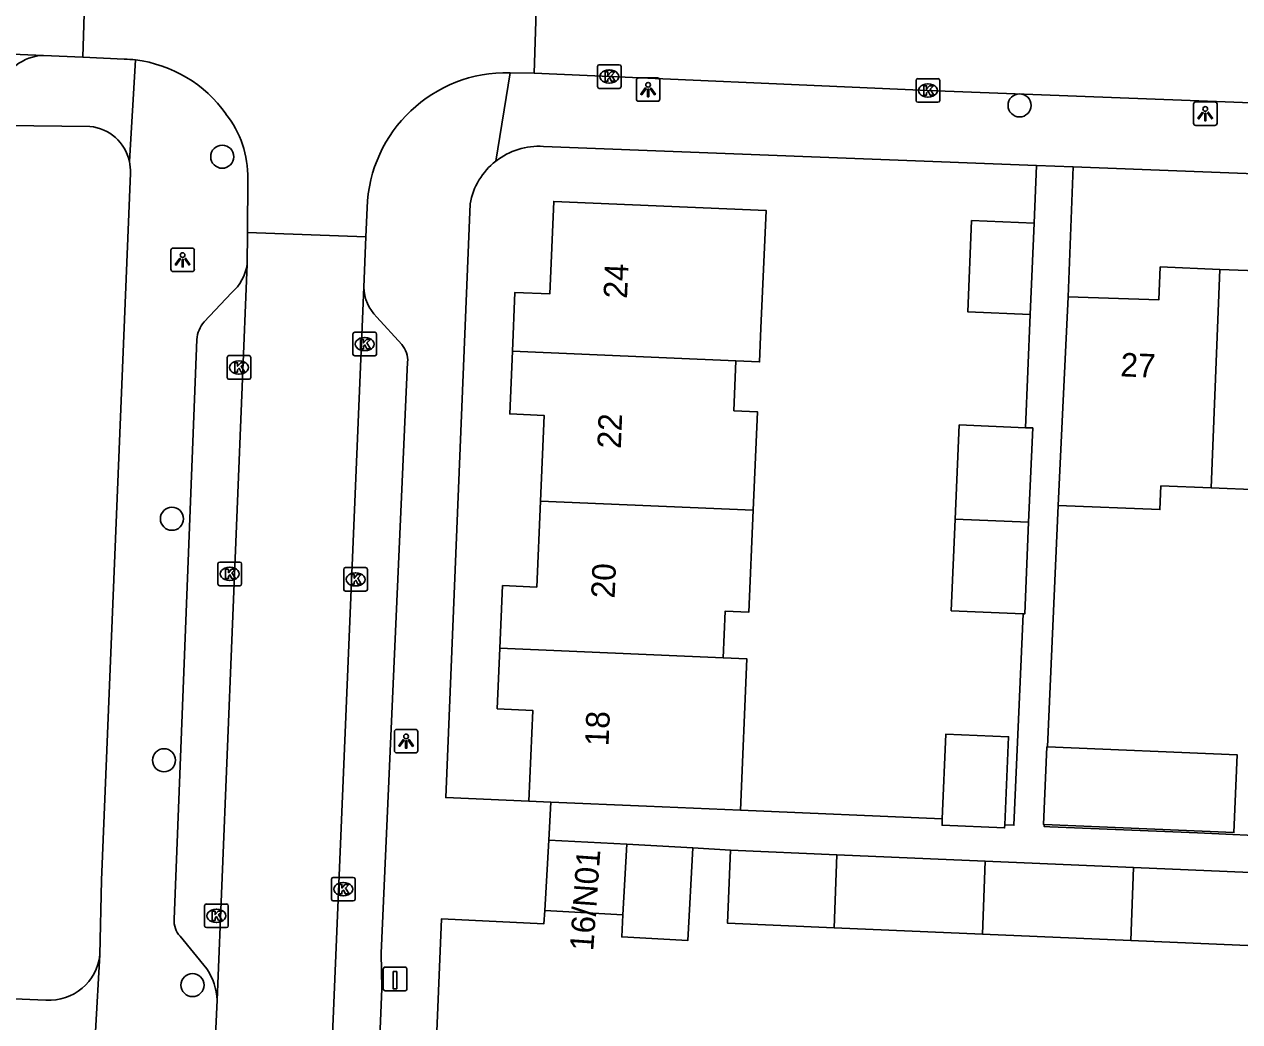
# Model space of a CAD drawing. Extents: x 160732 to 162105, y 387428 to 388479.
# Drawn here: x 161250.8 to 161302.4, y 387575 to 387617.3 of the extents above; entities that cross this region are included whole.
import ezdxf

# ---------------------------------------------------------------- set-up
doc = ezdxf.new("R2010")
doc.units = 0
for name, color, linetype in [('IMGEO_Boom', 7, 'Continuous'), ('IMGEO_Kolk', 7, 'Continuous'), ('IMGEO_Laadpaal', 7, 'Continuous'), ('IMGEO_Lichtpunt', 7, 'Continuous'), ('IMGEO_Pand', 7, 'Continuous'), ('IMGEO_Pand_nummerreeks', 7, 'Continuous'), ('IMGEO_Rijbaan_lokaal_open', 7, 'Continuous'), ('IMGEO_Voetpad_open', 7, 'Continuous')]:
    doc.layers.add(name, color=color, linetype=linetype)

msp = doc.modelspace()

# ---------------------------------------------------------------- linework, layer by layer
at = {"layer": 'IMGEO_Boom'}
for centre in [(161293.062, 387613.849), (161259.203, 387611.671), (161257.067, 387596.302), (161256.731, 387586.051), (161257.941, 387576.507)]:
    msp.add_circle(centre, 0.489, dxfattribs=at)
at = {"layer": 'IMGEO_Kolk'}
for p, q in [((161275.14, 387614.646), (161275.14, 387615.498)), ((161275.215, 387615.572), (161276.067, 387615.572)), ((161276.141, 387615.498), (161276.141, 387614.646)), ((161275.628, 387615.352), (161275.653, 387615.352)), ((161288.671, 387614.058), (161288.671, 387614.91)), ((161288.746, 387614.984), (161289.598, 387614.984)), ((161289.672, 387614.91), (161289.672, 387614.058)), ((161276.067, 387614.572), (161275.215, 387614.572)), ((161275.651, 387614.792), (161275.626, 387614.792)), ((161289.159, 387614.764), (161289.184, 387614.764)), ((161289.598, 387613.984), (161288.746, 387613.984)), ((161289.182, 387614.204), (161289.157, 387614.204)), ((161264.756, 387603.293), (161264.756, 387604.145)), ((161264.831, 387604.219), (161265.683, 387604.219)), ((161265.757, 387604.145), (161265.757, 387603.293)), ((161265.244, 387603.999), (161265.269, 387603.999)), ((161259.414, 387602.3), (161259.414, 387603.152)), ((161259.489, 387603.226), (161260.341, 387603.226)), ((161259.902, 387603.006), (161259.927, 387603.006)), ((161260.415, 387603.152), (161260.415, 387602.3)), ((161265.683, 387603.219), (161264.831, 387603.219)), ((161265.267, 387603.439), (161265.242, 387603.439)), ((161260.341, 387602.226), (161259.489, 387602.226)), ((161259.925, 387602.446), (161259.9, 387602.446)), ((161259.022, 387593.536), (161259.022, 387594.388)), ((161259.097, 387594.462), (161259.949, 387594.462)), ((161259.51, 387594.242), (161259.535, 387594.242)), ((161260.023, 387594.388), (161260.023, 387593.536)), ((161264.441, 387594.23), (161265.293, 387594.23)), ((161264.366, 387593.304), (161264.366, 387594.156)), ((161264.854, 387594.01), (161264.879, 387594.01)), ((161265.367, 387594.156), (161265.367, 387593.304)), ((161259.949, 387593.462), (161259.097, 387593.462)), ((161259.533, 387593.682), (161259.508, 387593.682)), ((161265.293, 387593.23), (161264.441, 387593.23)), ((161264.877, 387593.45), (161264.852, 387593.45)), ((161263.843, 387580.154), (161263.843, 387581.006)), ((161263.918, 387581.08), (161264.77, 387581.08)), ((161264.331, 387580.86), (161264.356, 387580.86)), ((161264.844, 387581.006), (161264.844, 387580.154)), ((161264.354, 387580.3), (161264.329, 387580.3)), ((161258.457, 387579.024), (161258.457, 387579.876)), ((161258.532, 387579.95), (161259.384, 387579.95)), ((161259.458, 387579.876), (161259.458, 387579.024)), ((161264.77, 387580.08), (161263.918, 387580.08)), ((161258.945, 387579.73), (161258.97, 387579.73)), ((161259.384, 387578.95), (161258.532, 387578.95)), ((161258.968, 387579.17), (161258.943, 387579.17))]:
    msp.add_line(p, q, dxfattribs=at)
for points in [[(161275.14, 387614.646), (161275.14, 387615.498)], [(161275.215, 387615.572), (161276.067, 387615.572)], [(161276.141, 387615.498), (161276.141, 387614.646)], [(161275.461, 387615.272), (161275.584, 387615.272), (161275.584, 387615.121), (161275.714, 387615.272), (161275.878, 387615.272), (161275.732, 387615.121), (161275.885, 387614.872), (161275.733, 387614.872), (161275.648, 387615.036), (161275.584, 387614.969), (161275.584, 387614.872), (161275.461, 387614.872), (161275.461, 387615.272)], [(161288.671, 387614.058), (161288.671, 387614.91)], [(161288.746, 387614.984), (161289.598, 387614.984)], [(161289.672, 387614.91), (161289.672, 387614.058)], [(161276.067, 387614.572), (161275.215, 387614.572)], [(161288.992, 387614.684), (161289.115, 387614.684), (161289.115, 387614.533), (161289.245, 387614.684), (161289.409, 387614.684), (161289.263, 387614.533), (161289.416, 387614.284), (161289.264, 387614.284), (161289.179, 387614.448), (161289.115, 387614.381), (161289.115, 387614.284), (161288.992, 387614.284), (161288.992, 387614.684)], [(161289.598, 387613.984), (161288.746, 387613.984)], [(161264.756, 387603.293), (161264.756, 387604.145)], [(161264.831, 387604.219), (161265.683, 387604.219)], [(161265.757, 387604.145), (161265.757, 387603.293)], [(161265.077, 387603.919), (161265.2, 387603.919), (161265.2, 387603.768), (161265.33, 387603.919), (161265.494, 387603.919), (161265.348, 387603.768), (161265.501, 387603.519), (161265.349, 387603.519), (161265.264, 387603.683), (161265.2, 387603.616), (161265.2, 387603.519), (161265.077, 387603.519), (161265.077, 387603.919)], [(161259.414, 387602.3), (161259.414, 387603.152)], [(161259.489, 387603.226), (161260.341, 387603.226)], [(161260.415, 387603.152), (161260.415, 387602.3)], [(161265.683, 387603.219), (161264.831, 387603.219)], [(161259.735, 387602.926), (161259.858, 387602.926), (161259.858, 387602.775), (161259.988, 387602.926), (161260.152, 387602.926), (161260.006, 387602.775), (161260.159, 387602.526), (161260.007, 387602.526), (161259.922, 387602.69), (161259.858, 387602.623), (161259.858, 387602.526), (161259.735, 387602.526), (161259.735, 387602.926)], [(161260.341, 387602.226), (161259.489, 387602.226)], [(161259.022, 387593.536), (161259.022, 387594.388)], [(161259.097, 387594.462), (161259.949, 387594.462)], [(161260.023, 387594.388), (161260.023, 387593.536)], [(161264.441, 387594.23), (161265.293, 387594.23)], [(161259.343, 387594.162), (161259.466, 387594.162), (161259.466, 387594.011), (161259.596, 387594.162), (161259.76, 387594.162), (161259.614, 387594.011), (161259.767, 387593.762), (161259.615, 387593.762), (161259.53, 387593.926), (161259.466, 387593.859), (161259.466, 387593.762), (161259.343, 387593.762), (161259.343, 387594.162)], [(161264.366, 387593.304), (161264.366, 387594.156)], [(161264.687, 387593.93), (161264.81, 387593.93), (161264.81, 387593.779), (161264.94, 387593.93), (161265.104, 387593.93), (161264.958, 387593.779), (161265.111, 387593.53), (161264.959, 387593.53), (161264.874, 387593.694), (161264.81, 387593.627), (161264.81, 387593.53), (161264.687, 387593.53), (161264.687, 387593.93)], [(161265.367, 387594.156), (161265.367, 387593.304)], [(161259.949, 387593.462), (161259.097, 387593.462)], [(161265.293, 387593.23), (161264.441, 387593.23)], [(161263.843, 387580.154), (161263.843, 387581.006)], [(161263.918, 387581.08), (161264.77, 387581.08)], [(161264.844, 387581.006), (161264.844, 387580.154)], [(161264.164, 387580.78), (161264.287, 387580.78), (161264.287, 387580.629), (161264.417, 387580.78), (161264.581, 387580.78), (161264.435, 387580.629), (161264.588, 387580.38), (161264.436, 387580.38), (161264.351, 387580.544), (161264.287, 387580.477), (161264.287, 387580.38), (161264.164, 387580.38), (161264.164, 387580.78)], [(161258.457, 387579.024), (161258.457, 387579.876)], [(161258.532, 387579.95), (161259.384, 387579.95)], [(161259.458, 387579.876), (161259.458, 387579.024)], [(161264.77, 387580.08), (161263.918, 387580.08)], [(161258.778, 387579.65), (161258.901, 387579.65), (161258.901, 387579.499), (161259.031, 387579.65), (161259.195, 387579.65), (161259.049, 387579.499), (161259.202, 387579.25), (161259.05, 387579.25), (161258.965, 387579.414), (161258.901, 387579.347), (161258.901, 387579.25), (161258.778, 387579.25), (161258.778, 387579.65)], [(161259.384, 387578.95), (161258.532, 387578.95)]]:
    msp.add_lwpolyline(points, dxfattribs=at)
for centre, start, end in [((161275.217, 387615.496), 91.552, 178.448), ((161275.217, 387615.496), 91.552, 178.448), ((161276.065, 387615.496), 1.552, 88.448), ((161276.065, 387615.496), 1.552, 88.448), ((161288.748, 387614.908), 91.552, 178.448), ((161288.748, 387614.908), 91.552, 178.448), ((161289.596, 387614.908), 1.552, 88.448), ((161289.596, 387614.908), 1.552, 88.448), ((161275.217, 387614.648), 181.552, 268.448), ((161275.217, 387614.648), 181.552, 268.448), ((161276.065, 387614.648), 271.552, 358.448), ((161276.065, 387614.648), 271.552, 358.448), ((161288.748, 387614.06), 181.552, 268.448), ((161288.748, 387614.06), 181.552, 268.448), ((161289.596, 387614.06), 271.552, 358.448), ((161289.596, 387614.06), 271.552, 358.448), ((161264.833, 387604.143), 91.552, 178.448), ((161264.833, 387604.143), 91.552, 178.448), ((161265.681, 387604.143), 1.552, 88.448), ((161265.681, 387604.143), 1.552, 88.448), ((161259.491, 387603.15), 91.552, 178.448), ((161259.491, 387603.15), 91.552, 178.448), ((161260.339, 387603.15), 1.552, 88.448), ((161260.339, 387603.15), 1.552, 88.448), ((161264.833, 387603.295), 181.552, 268.448), ((161264.833, 387603.295), 181.552, 268.448), ((161265.681, 387603.295), 271.552, 358.448), ((161265.681, 387603.295), 271.552, 358.448), ((161259.491, 387602.302), 181.552, 268.448), ((161259.491, 387602.302), 181.552, 268.448), ((161260.339, 387602.302), 271.552, 358.448), ((161260.339, 387602.302), 271.552, 358.448), ((161259.099, 387594.386), 91.552, 178.448), ((161259.099, 387594.386), 91.552, 178.448), ((161259.947, 387594.386), 1.552, 88.448), ((161259.947, 387594.386), 1.552, 88.448), ((161264.443, 387594.154), 91.552, 178.448), ((161264.443, 387594.154), 91.552, 178.448), ((161265.291, 387594.154), 1.552, 88.448), ((161265.291, 387594.154), 1.552, 88.448), ((161259.099, 387593.538), 181.552, 268.448), ((161259.099, 387593.538), 181.552, 268.448), ((161259.947, 387593.538), 271.552, 358.448), ((161259.947, 387593.538), 271.552, 358.448), ((161264.443, 387593.306), 181.552, 268.448), ((161264.443, 387593.306), 181.552, 268.448), ((161265.291, 387593.306), 271.552, 358.448), ((161265.291, 387593.306), 271.552, 358.448), ((161263.92, 387581.004), 91.552, 178.448), ((161263.92, 387581.004), 91.552, 178.448), ((161264.768, 387581.004), 1.552, 88.448), ((161264.768, 387581.004), 1.552, 88.448), ((161258.534, 387579.874), 91.552, 178.448), ((161258.534, 387579.874), 91.552, 178.448), ((161259.382, 387579.874), 1.552, 88.448), ((161259.382, 387579.874), 1.552, 88.448), ((161263.92, 387580.156), 181.552, 268.448), ((161263.92, 387580.156), 181.552, 268.448), ((161264.768, 387580.156), 271.552, 358.448), ((161264.768, 387580.156), 271.552, 358.448), ((161258.534, 387579.026), 181.552, 268.448), ((161258.534, 387579.026), 181.552, 268.448), ((161259.382, 387579.026), 271.552, 358.448), ((161259.382, 387579.026), 271.552, 358.448)]:
    msp.add_arc(centre, 0.0765, start, end, dxfattribs=at)
for centre, major_axis, ratio, start_param, end_param in [((161275.627, 387615.072), (-0.387, 0.002), 0.722429, 4.712389, 7.853982), ((161275.652, 387615.072), (-0.39, 0.002), 0.717154, 1.570796, 4.712389), ((161289.158, 387614.484), (-0.387, 0.002), 0.722429, 4.712389, 7.853982), ((161289.183, 387614.484), (-0.39, 0.002), 0.717154, 1.570796, 4.712389), ((161265.243, 387603.719), (-0.387, 0.002), 0.722429, 4.712389, 7.853982), ((161265.268, 387603.719), (-0.39, 0.002), 0.717154, 1.570796, 4.712389), ((161259.901, 387602.726), (-0.387, 0.002), 0.722429, 4.712389, 7.853982), ((161259.926, 387602.726), (-0.39, 0.002), 0.717154, 1.570796, 4.712389), ((161259.509, 387593.962), (-0.387, 0.002), 0.722429, 4.712389, 7.853982), ((161259.534, 387593.962), (-0.39, 0.002), 0.717154, 1.570796, 4.712389), ((161264.853, 387593.73), (-0.387, 0.002), 0.722429, 4.712389, 7.853982), ((161264.878, 387593.73), (-0.39, 0.002), 0.717154, 1.570796, 4.712389), ((161264.33, 387580.58), (-0.387, 0.002), 0.722429, 4.712389, 7.853982), ((161264.355, 387580.58), (-0.39, 0.002), 0.717154, 1.570796, 4.712389), ((161258.944, 387579.45), (-0.387, 0.002), 0.722429, 4.712389, 7.853982), ((161258.969, 387579.45), (-0.39, 0.002), 0.717154, 1.570796, 4.712389)]:
    msp.add_ellipse(centre, major_axis=major_axis, ratio=ratio, start_param=start_param, end_param=end_param, dxfattribs=at)
at = {"layer": 'IMGEO_Laadpaal'}
for p, q in [((161266.959, 387577.27), (161266.118, 387577.27)), ((161266.959, 387577.27), (161266.118, 387577.27)), ((161267.043, 387576.354), (161267.043, 387577.195)), ((161267.043, 387576.354), (161267.043, 387577.195)), ((161266.043, 387577.186), (161266.043, 387576.345)), ((161266.043, 387577.186), (161266.043, 387576.345)), ((161266.127, 387576.27), (161266.968, 387576.27)), ((161266.127, 387576.27), (161266.968, 387576.27))]:
    msp.add_line(p, q, dxfattribs=at)
msp.add_lwpolyline([(161266.458, 387577.083), (161266.618, 387577.083), (161266.618, 387576.35), (161266.458, 387576.35), (161266.458, 387577.083)], dxfattribs=at)
for centre, start, end in [((161266.121, 387577.192), 92.4484, 184.2845), ((161266.121, 387577.192), 92.4484, 184.2845), ((161266.965, 387577.192), 2.4484, 94.2845), ((161266.965, 387577.192), 2.4484, 94.2845), ((161266.121, 387576.348), 182.4484, 274.2845), ((161266.121, 387576.348), 182.4484, 274.2845), ((161266.965, 387576.348), 272.4484, 4.2845), ((161266.965, 387576.348), 272.4484, 4.2845)]:
    msp.add_arc(centre, 0.0779, start, end, dxfattribs=at)
at = {"layer": 'IMGEO_Lichtpunt'}
for p, q in [((161276.791, 387614.924), (161276.791, 387614.117)), ((161276.791, 387614.924), (161276.791, 387614.117)), ((161277.693, 387615.019), (161276.885, 387615.019)), ((161277.693, 387615.019), (161276.885, 387615.019)), ((161277.787, 387614.117), (161277.787, 387614.924)), ((161277.787, 387614.117), (161277.787, 387614.924)), ((161276.885, 387614.023), (161277.693, 387614.023)), ((161276.885, 387614.023), (161277.693, 387614.023)), ((161300.452, 387613.902), (161300.452, 387613.095)), ((161300.452, 387613.902), (161300.452, 387613.095)), ((161301.354, 387613.997), (161300.546, 387613.997)), ((161301.354, 387613.997), (161300.546, 387613.997)), ((161301.448, 387613.095), (161301.448, 387613.902)), ((161301.448, 387613.095), (161301.448, 387613.902)), ((161300.546, 387613.001), (161301.354, 387613.001)), ((161300.546, 387613.001), (161301.354, 387613.001)), ((161257.023, 387607.699), (161257.023, 387606.892)), ((161257.023, 387607.699), (161257.023, 387606.892)), ((161257.925, 387607.794), (161257.117, 387607.794)), ((161257.925, 387607.794), (161257.117, 387607.794)), ((161258.019, 387606.892), (161258.019, 387607.699)), ((161258.019, 387606.892), (161258.019, 387607.699)), ((161257.117, 387606.798), (161257.925, 387606.798)), ((161257.117, 387606.798), (161257.925, 387606.798)), ((161266.514, 387587.265), (161266.514, 387586.458)), ((161266.514, 387587.265), (161266.514, 387586.458)), ((161267.416, 387587.36), (161266.608, 387587.36)), ((161267.416, 387587.36), (161266.608, 387587.36)), ((161267.51, 387586.458), (161267.51, 387587.265)), ((161267.51, 387586.458), (161267.51, 387587.265)), ((161266.608, 387586.364), (161267.416, 387586.364)), ((161266.608, 387586.364), (161267.416, 387586.364))]:
    msp.add_line(p, q, dxfattribs=at)
for points in [[(161277.165, 387614.588), (161277.204, 387614.56), (161277.016, 387614.298), (161276.978, 387614.325), (161277.165, 387614.588)], [(161277.267, 387614.54), (161277.314, 387614.54), (161277.314, 387614.218), (161277.267, 387614.218), (161277.267, 387614.54)], [(161277.377, 387614.56), (161277.415, 387614.587), (161277.602, 387614.325), (161277.563, 387614.297), (161277.377, 387614.56)], [(161300.826, 387613.566), (161300.865, 387613.538), (161300.677, 387613.276), (161300.639, 387613.303), (161300.826, 387613.566)], [(161300.928, 387613.518), (161300.975, 387613.518), (161300.975, 387613.196), (161300.928, 387613.196), (161300.928, 387613.518)], [(161301.038, 387613.538), (161301.076, 387613.565), (161301.263, 387613.303), (161301.224, 387613.275), (161301.038, 387613.538)], [(161257.397, 387607.363), (161257.436, 387607.335), (161257.248, 387607.073), (161257.21, 387607.1), (161257.397, 387607.363)], [(161257.499, 387607.315), (161257.546, 387607.315), (161257.546, 387606.993), (161257.499, 387606.993), (161257.499, 387607.315)], [(161257.609, 387607.335), (161257.647, 387607.362), (161257.834, 387607.1), (161257.795, 387607.072), (161257.609, 387607.335)], [(161266.888, 387586.929), (161266.927, 387586.901), (161266.739, 387586.639), (161266.701, 387586.666), (161266.888, 387586.929)], [(161266.99, 387586.881), (161267.037, 387586.881), (161267.037, 387586.559), (161266.99, 387586.559), (161266.99, 387586.881)], [(161267.1, 387586.901), (161267.138, 387586.928), (161267.325, 387586.666), (161267.286, 387586.638), (161267.1, 387586.901)]]:
    msp.add_lwpolyline(points, dxfattribs=at)
for centre in [(161277.29, 387614.722), (161300.951, 387613.7), (161257.522, 387607.497), (161267.013, 387587.063)]:
    msp.add_circle(centre, 0.0994, dxfattribs=at)
for centre, start, end in [((161276.885, 387614.924), 90, 180), ((161276.885, 387614.924), 90, 180), ((161277.693, 387614.924), 0, 90), ((161277.693, 387614.924), 0, 90), ((161276.885, 387614.117), 180, 270), ((161276.885, 387614.117), 180, 270), ((161277.693, 387614.117), 270, 0), ((161277.693, 387614.117), 270, 360), ((161300.546, 387613.902), 90, 180), ((161300.546, 387613.902), 90, 180), ((161301.354, 387613.902), 0, 90), ((161301.354, 387613.902), 0, 90), ((161300.546, 387613.095), 180, 270), ((161300.546, 387613.095), 180, 270), ((161301.354, 387613.095), 270, 0), ((161301.354, 387613.095), 270, 360), ((161257.117, 387607.699), 90, 180), ((161257.117, 387607.699), 90, 180), ((161257.925, 387607.699), 0, 90), ((161257.925, 387607.699), 0, 90), ((161257.117, 387606.892), 180, 270), ((161257.117, 387606.892), 180, 270), ((161257.925, 387606.892), 270, 0), ((161257.925, 387606.892), 270, 360), ((161266.608, 387587.265), 90, 180), ((161266.608, 387587.265), 90, 180), ((161267.416, 387587.265), 0, 90), ((161267.416, 387587.265), 0, 90), ((161266.608, 387586.458), 180, 270), ((161266.608, 387586.458), 180, 270), ((161267.416, 387586.458), 270, 0), ((161267.416, 387586.458), 270, 360)]:
    msp.add_arc(centre, 0.0946, start, end, dxfattribs=at)
at = {"layer": 'IMGEO_Pand'}
for points in [[(161271.53, 387603.417), (161271.636, 387605.91), (161273.114, 387605.847), (161273.282, 387609.775), (161282.296, 387609.389), (161282.082, 387604.394), (161282.021, 387602.964), (161281.021, 387603.007)], [(161293.518, 387604.977), (161290.86, 387605.09), (161291.025, 387608.958), (161293.683, 387608.845)], [(161293.683, 387608.845), (161293.518, 387604.977)], [(161295.134, 387605.725), (161298.979, 387605.598), (161299.035, 387606.991), (161301.569, 387606.89)], [(161301.2, 387597.613), (161301.569, 387606.89)], [(161301.569, 387606.89), (161304.303, 387606.782), (161304.245, 387605.331), (161307.807, 387605.189)], [(161294.699, 387596.865), (161294.889, 387600.732), (161295.134, 387605.725)], [(161272.718, 387597.051), (161272.873, 387600.693), (161271.416, 387600.756), (161271.53, 387603.417)], [(161271.53, 387603.417), (161281.021, 387603.007)], [(161281.021, 387603.007), (161280.93, 387600.886), (161281.93, 387600.843), (161281.751, 387596.661)], [(161290.33, 387596.291), (161290.502, 387600.289), (161293.313, 387600.169)], [(161293.45, 387596.156), (161293.621, 387600.156), (161293.313, 387600.169)], [(161301.2, 387597.613), (161299.067, 387597.699), (161299.026, 387596.69), (161294.699, 387596.865)], [(161307.455, 387596.343), (161303.206, 387596.519), (161303.248, 387597.53), (161301.2, 387597.613)], [(161270.992, 387590.81), (161271.106, 387593.468), (161272.562, 387593.406), (161272.718, 387597.051)], [(161272.718, 387597.051), (161281.751, 387596.661)], [(161281.751, 387596.661), (161281.567, 387592.341), (161280.568, 387592.383), (161280.483, 387590.4)], [(161293.213, 387592.265), (161290.164, 387592.396), (161290.33, 387596.291)], [(161290.33, 387596.291), (161293.45, 387596.156)], [(161293.213, 387592.265), (161293.283, 387592.262), (161293.45, 387596.156)], [(161272.229, 387584.319), (161272.394, 387588.17), (161270.882, 387588.235), (161270.992, 387590.81)], [(161280.483, 387590.4), (161270.992, 387590.81)], [(161280.483, 387590.4), (161281.482, 387590.357), (161281.207, 387583.935)], [(161289.783, 387583.569), (161289.936, 387587.161), (161292.594, 387587.048), (161292.435, 387583.31)], [(161294.114, 387583.32), (161294.085, 387583.321), (161294.224, 387586.624), (161294.256, 387586.623)], [(161294.256, 387586.623), (161302.303, 387586.286), (161302.165, 387582.982), (161294.114, 387583.32)], [(161273.16, 387584.279), (161272.229, 387584.319)], [(161281.207, 387583.935), (161277.225, 387584.105), (161273.16, 387584.279)], [(161292.435, 387583.31), (161292.429, 387583.18), (161289.771, 387583.293), (161289.783, 387583.569)], [(161272.905, 387579.671), (161273.067, 387582.666)], [(161273.067, 387582.666), (161276.384, 387582.486)], [(161276.222, 387579.491), (161276.384, 387582.486)], [(161276.384, 387582.486), (161279.188, 387582.334)], [(161276.222, 387579.491), (161276.171, 387578.55), (161278.975, 387578.398), (161279.188, 387582.334)], [(161280.791, 387582.236), (161280.657, 387579.141), (161285.186, 387578.945)], [(161280.791, 387582.236), (161285.302, 387582.042)], [(161285.302, 387582.042), (161285.186, 387578.945)], [(161285.302, 387582.042), (161291.6, 387581.769)], [(161291.483, 387578.673), (161291.6, 387581.769)], [(161291.6, 387581.769), (161297.898, 387581.497)], [(161297.898, 387581.497), (161297.782, 387578.401)], [(161297.898, 387581.497), (161304.196, 387581.225)], [(161272.905, 387579.671), (161276.222, 387579.491)], [(161285.186, 387578.945), (161291.483, 387578.673)], [(161291.483, 387578.673), (161297.782, 387578.401)], [(161297.782, 387578.401), (161304.079, 387578.129)]]:
    msp.add_lwpolyline(points, dxfattribs=at)
at = {"layer": 'IMGEO_Rijbaan_lokaal_open'}
for points in [[(161253.433, 387620.949), (161253.289, 387615.895)], [(161272.446, 387615.211), (161272.605, 387620.102)], [(161251.616, 387615.972), (161235.056, 387616.672)], [(161253.289, 387615.895), (161251.616, 387615.972)], [(161253.289, 387615.895), (161255.043, 387615.814)], [(161271.428, 387615.232), (161272.446, 387615.211)], [(161343.203, 387612.394), (161312.936, 387613.577), (161289.172, 387614.484), (161272.446, 387615.211)], [(161260.287, 387610.735), (161260.275, 387608.45)], [(161265.309, 387608.273), (161265.357, 387609.499)], [(161260.267, 387607.109), (161260.275, 387608.45)], [(161260.275, 387608.45), (161265.309, 387608.273)], [(161265.309, 387608.273), (161265.221, 387606.137)], [(161258.993, 387575.867), (161260.267, 387607.109)], [(161265.221, 387606.137), (161263.113, 387555.827)], [(161258.836, 387572.551), (161258.993, 387575.867)]]:
    msp.add_lwpolyline(points, dxfattribs=at)
for centre, radius, start, end in [((161254.852, 387610.073), 5.744, 83.3055, 88.0983), ((161254.868, 387610.321), 5.496, 35.1084, 83.1661), ((161271.275, 387609.313), 5.921, 88.5203, 178.1993), ((161256.018, 387610.829), 4.27, 358.7373, 38.4077)]:
    msp.add_arc(centre, radius, start, end, dxfattribs=at)
at = {"layer": 'IMGEO_Voetpad_open'}
for points in [[(161255.522, 387615.778), (161255.263, 387611.475)], [(161270.821, 387611.482), (161271.428, 387615.232)], [(161228.273, 387613.957), (161250.02, 387612.998), (161253.586, 387612.955)], [(161293.778, 387611.304), (161272.842, 387612.109)], [(161293.683, 387608.845), (161293.778, 387611.304)], [(161295.346, 387611.244), (161293.778, 387611.304)], [(161255.307, 387610.978), (161254.07, 387580.964), (161254.012, 387577.793)], [(161295.346, 387611.244), (161295.134, 387605.725)], [(161350.027, 387609.14), (161295.346, 387611.244)], [(161269.729, 387609.67), (161268.695, 387584.47), (161272.229, 387584.319)], [(161258.433, 387604.66), (161259.604, 387605.895)], [(161265.767, 387604.866), (161266.825, 387603.697)], [(161293.313, 387600.169), (161293.518, 387604.977)], [(161257.161, 387579.305), (161258.126, 387603.916)], [(161267.078, 387602.949), (161265.956, 387577.857), (161265.979, 387576.363), (161265.254, 387558.747)], [(161294.699, 387596.865), (161294.256, 387586.623)], [(161292.435, 387583.31), (161292.825, 387583.294), (161293.213, 387592.265)], [(161273.067, 387582.666), (161273.16, 387584.279)], [(161281.207, 387583.935), (161289.783, 387583.569)], [(161294.114, 387583.32), (161294.11, 387583.238), (161294.347, 387583.228), (161300.618, 387582.965), (161303.023, 387582.864)], [(161279.188, 387582.334), (161280.791, 387582.236)], [(161267.578, 387556.812), (161268.51, 387579.316), (161272.863, 387579.112), (161272.905, 387579.671)], [(161258.552, 387577.195), (161257.418, 387578.581)], [(161254.012, 387577.793), (161253.645, 387571.282)], [(161226.791, 387576.922), (161251.719, 387575.864)]]:
    msp.add_lwpolyline(points, dxfattribs=at)
for centre, radius, start, end in [((161251.671, 387613.996), 1.977, 91.6048, 128.6421), ((161253.406, 387611.06), 1.903, 12.5829, 84.5585), ((161272.657, 387609.136), 2.979, 86.4334, 128.0388), ((161253.364, 387611.056), 1.944, 357.6879, 12.4306), ((161272.653, 387609.143), 2.972, 128.0717, 169.7779), ((161258.266, 387607.414), 2.024, 311.3813, 351.3383), ((161267.01, 387606.153), 1.789, 180.5022, 225.9928), ((161259.376, 387603.835), 1.253, 138.8424, 176.3122), ((161266.098, 387603.034), 0.984, 355.0286, 42.3461), ((161258.108, 387579.234), 0.95, 175.6933, 223.3937), ((161251.844, 387578.043), 2.183, 266.7239, 353.421), ((161256.296, 387575.709), 2.701, 3.3591, 33.3814)]:
    msp.add_arc(centre, radius, start, end, dxfattribs=at)

# ---------------------------------------------------------------- texts
at = {"layer": 'IMGEO_Pand_nummerreeks'}
for s, rotation, p in [('24', 87.6339, (161276.393, 387605.632)), ('27', 357.6165, (161297.332, 387602.351)), ('22', 87.6339, (161276.13, 387599.265)), ('20', 87.6339, (161275.867, 387592.907)), ('18', 87.6339, (161275.607, 387586.634)), ('16/N01', 85.9144, (161274.958, 387577.932))]:
    msp.add_text(s, height=1, rotation=rotation, dxfattribs=at).set_placement(p)

doc.saveas('drawing.dxf')
